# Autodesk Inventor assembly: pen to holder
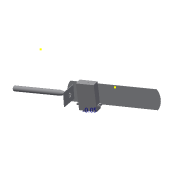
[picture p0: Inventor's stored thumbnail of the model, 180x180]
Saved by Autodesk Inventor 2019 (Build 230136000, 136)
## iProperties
Created: 2020-02
Part Number: pen to holder
Document SubType Name: Assembly
Designer: Krupashree
Author: Krupashree
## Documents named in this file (4)
- A:\sec sem notes\Engg explorRION\MODELLING\pen to holder.iam
- A:\sec sem notes\Engg explorRION\MODELLING\motor to pen.iam
- A:\sec sem notes\Engg explorRION\MODELLING\servo motor latest.ipt
- A:\sec sem notes\Engg explorRION\MODELLING\pen.ipt
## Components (3 placed, 3 different names)
1. motor to pen:1 [sub-assembly] — Mate:1, Mate:2, Mate:3
2. servo motor latest:1 — Mate:1
3. pen:1 — Mate:2, Mate:3
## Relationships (3: Mate 3)
- Mate:1: motor to pen:1 ↔ servo motor latest:1
- Mate:2: motor to pen:1 ↔ pen:1
- Mate:3: motor to pen:1 ↔ pen:1
